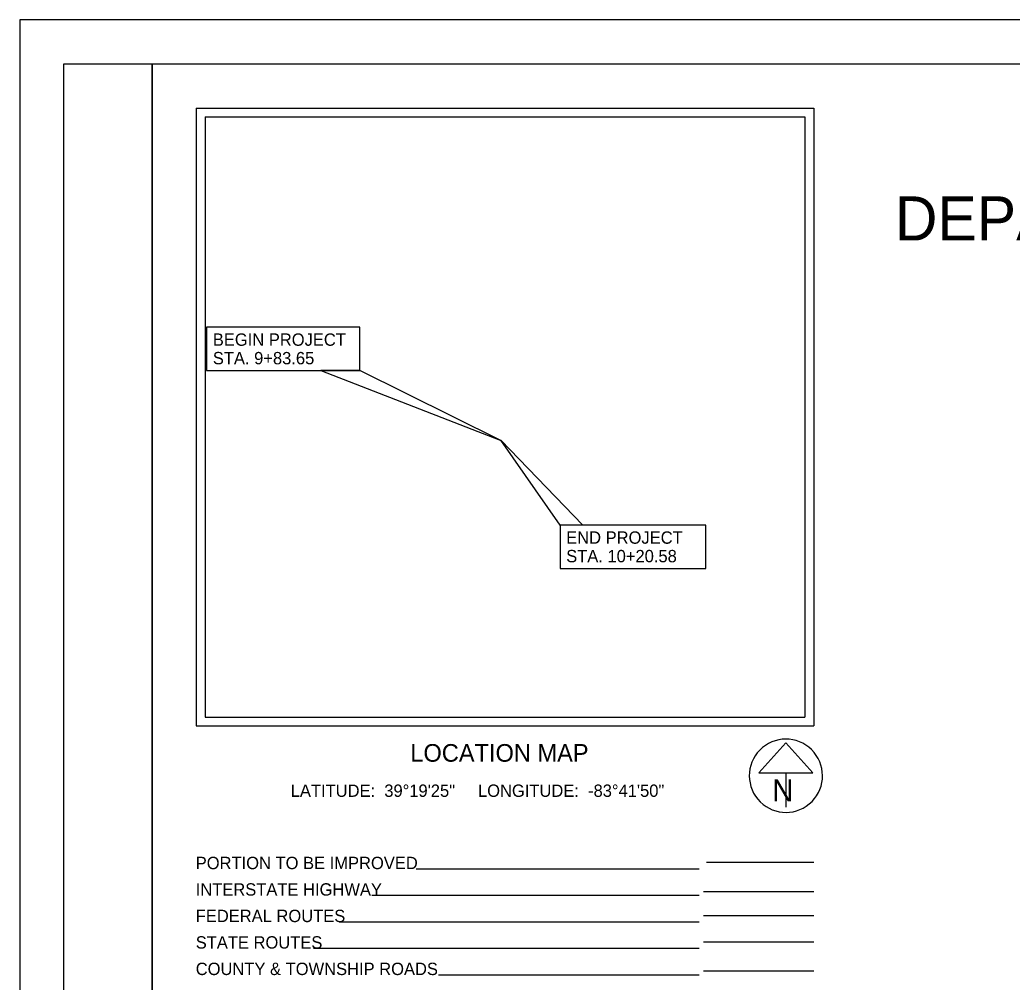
# Model space of a CAD drawing. Extents: x 0 to 40.9, y 0 to 22.
# Drawn here: x 0 to 11.25, y 11.1 to 22 of the extents above; entities that cross this region are included whole.
import ezdxf

# ---------------------------------------------------------------- set-up
doc = ezdxf.new("R2010")
doc.units = 0
for name, color, linetype in [('SH_Border', 7, 'Continuous'), ('SH_Cut_Line', 7, 'Continuous'), ('SH_Data', 7, 'Continuous'), ('SH_Text', 7, 'Continuous')]:
    doc.layers.add(name, color=color, linetype=linetype)

msp = doc.modelspace()

# ---------------------------------------------------------------- linework, layer by layer
at = {"layer": 'SH_Border'}
for points in [[(2.118, 18.027), (3.854, 18.027), (3.854, 18.517), (2.118, 18.517)], [(6.124, 15.784), (7.779, 15.784), (7.779, 16.274), (6.124, 16.274)]]:
    msp.add_lwpolyline(points, close=True, dxfattribs=at)
at = {"layer": 'SH_Cut_Line'}
for p, q in [((2, 21), (9, 21)), ((2, 21), (2, 14)), ((9, 21), (9, 14)), ((2.1, 20.9), (2.1, 14.1)), ((2.1, 20.9), (8.9, 20.9)), ((8.9, 20.9), (8.9, 14.1)), ((5.445, 17.237), (5.452, 17.237)), ((2.1, 14.1), (8.9, 14.1)), ((2.1, 14.1), (2.1, 14.1)), ((2, 14), (9, 14)), ((8.685, 13.809), (8.377, 13.468)), ((8.992, 13.468), (8.685, 13.809)), ((8.377, 13.468), (8.992, 13.468)), ((8.685, 13.468), (8.685, 13.081)), ((8.685, 13.435), (8.685, 13.435)), ((8.685, 13.435), (8.685, 13.435)), ((7.7, 12.377), (4.494, 12.377)), ((7.783, 12.455), (9, 12.455)), ((7.7, 12.077), (3.99, 12.077)), ((9, 12.121), (7.75, 12.121)), ((9, 11.849), (7.75, 11.849)), ((7.7, 11.777), (3.619, 11.777)), ((7.7, 11.477), (3.329, 11.477)), ((9, 11.549), (7.75, 11.549)), ((7.7, 11.177), (4.745, 11.177)), ((9, 11.222), (7.75, 11.222))]:
    msp.add_line(p, q, dxfattribs=at)
for points in [[(3.414, 18.027), (5.445, 17.237), (3.854, 18.027)], [(6.124, 16.274), (5.452, 17.237), (6.382, 16.274)]]:
    msp.add_lwpolyline(points, close=True, dxfattribs=at)
msp.add_arc((8.685, 13.435), 0.415, 129.7798, 129.7633, dxfattribs=at)
at = {"layer": 'SH_Data'}
msp.add_lwpolyline([(0, 0), (34, 0), (34, 22), (0, 22)], close=True, dxfattribs=at)
at = {"layer": 'SH_Text'}
for points in [[(0.5, 21.5), (1.5, 21.5), (1.5, 0.5), (0.5, 0.5)], [(1.5, 21.5), (33.5, 21.5), (33.5, 0.5), (1.5, 0.5)]]:
    msp.add_lwpolyline(points, close=True, dxfattribs=at)

# ---------------------------------------------------------------- texts
at = {"layer": 'SH_Border'}
for s, height, p in [('DEPARTMENT OF TRANSPORTATION', 0.5, (9.92, 19.5)), ('BEGIN PROJECT', 0.14, (2.188, 18.307)), ('STA. 9+83.65', 0.14, (2.188, 18.097)), ('END PROJECT', 0.14, (6.194, 16.064)), ('STA. 10+20.58', 0.14, (6.194, 15.854)), ('LOCATION MAP', 0.2, (4.427, 13.594)), ('LATITUDE:  39°19\'25"     LONGITUDE:  -83°41\'50"', 0.14, (3.071, 13.196)), ('PORTION TO BE IMPROVED', 0.14, (1.994, 12.377)), ('INTERSTATE HIGHWAY', 0.14, (1.994, 12.077)), ('FEDERAL ROUTES', 0.14, (1.994, 11.777)), ('STATE ROUTES', 0.14, (1.994, 11.477)), ('COUNTY & TOWNSHIP ROADS', 0.14, (1.994, 11.177))]:
    msp.add_text(s, height=height, dxfattribs=at).set_placement(p)
at = {"layer": 'SH_Cut_Line'}
msp.add_text('N', height=0.25, dxfattribs=at).set_placement((8.529, 13.144))

doc.saveas('drawing.dxf')
